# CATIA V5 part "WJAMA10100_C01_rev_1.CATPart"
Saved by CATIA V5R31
Part number: WJAMA10100_C01_rev_1
Source: Unknown
Bounding box of the stored display mesh (mm): x 4191.626 to 4282.551, y 304.615 to 517.8, z 702.6 to 839.864
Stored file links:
  \\solize.local\damia\dept\DDE_Design\10_order\2305701_JAMA_変換検証STEP3_お手本モデル作成\work\02_マツダ_板金\10_CATIA_V5\231211\WJAMA10100_C01_rev_1.CATPart

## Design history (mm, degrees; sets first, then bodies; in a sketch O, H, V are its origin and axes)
TTRSSet1
f4a2d38f3ddc11d3a929006094b99c4b_11 "CATTPSSet"
Set1
  Point1 "CARTESIAN_POINT #37092": stored without definition
  Point2 "CARTESIAN_POINT #37093": stored without definition
  Point3 "CARTESIAN_POINT #37094": stored without definition
  Point4 "CARTESIAN_POINT #37095": stored without definition
  Point5 "CARTESIAN_POINT #37096": stored without definition
Body1 (main body)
